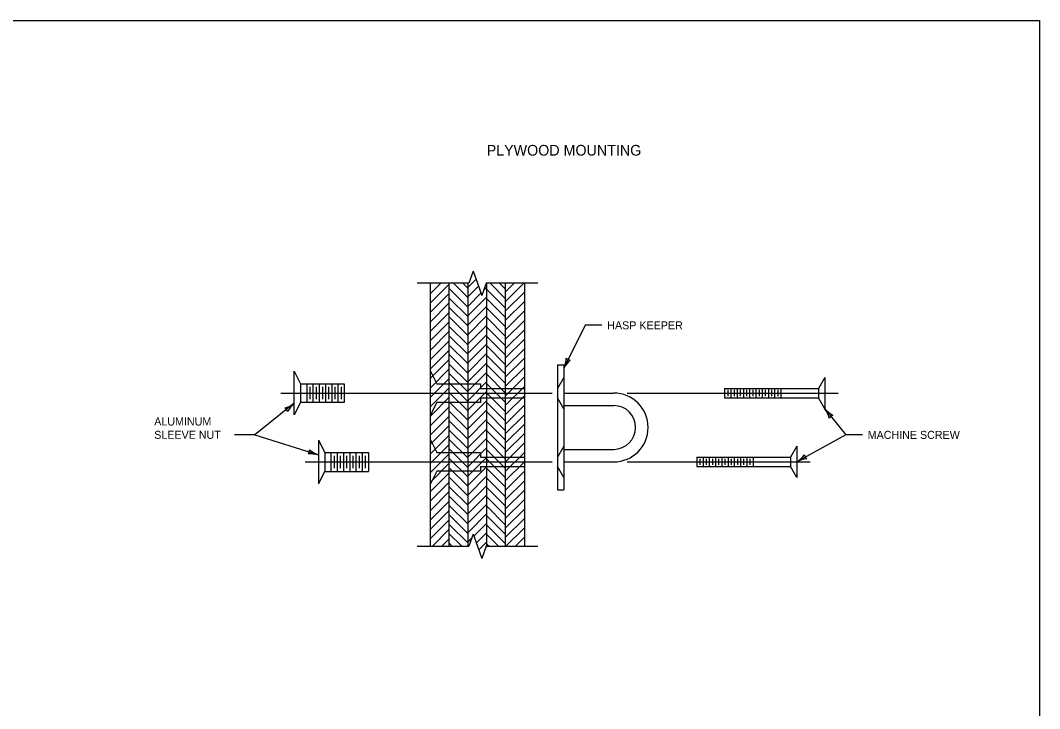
# Model space of a CAD drawing. Extents: x 49991.4 to 50021, y 49987.6 to 50011.4.
# Drawn here: x 50009.11 to 50016.75, y 49993.84 to 49999 of the extents above; entities that cross this region are included whole.
import ezdxf

# ---------------------------------------------------------------- set-up
doc = ezdxf.new("R2010")
doc.units = 0
for name, color, linetype in [('Level 1', 7, 'Continuous'), ('Level 2', 7, 'Continuous'), ('Level 3', 7, 'Continuous'), ('Level 4', 7, 'Continuous'), ('Level 5', 7, 'Continuous'), ('Level 6', 7, 'Continuous')]:
    doc.layers.add(name, color=color, linetype=linetype)

msp = doc.modelspace()

# ---------------------------------------------------------------- linework, layer by layer
at = {"layer": 'Level 1'}
for p, q in [((50012.4648, 49996.9989), (50012.5245, 49997.0586)), ((50012.1836, 49995.0568), (50012.1836, 49997.0284)), ((50012.1836, 49996.9521), (50012.2599, 49997.0284)), ((50012.1836, 49996.8814), (50012.3242, 49997.022)), ((50012.3242, 49995.0568), (50012.3242, 49997.0284)), ((50012.3242, 49996.988), (50012.4648, 49996.8474)), ((50012.3545, 49997.0284), (50012.4648, 49996.9181)), ((50012.4252, 49997.0284), (50012.4648, 49996.9888)), ((50012.4648, 49995.0568), (50012.4648, 49997.0284)), ((50012.4648, 49996.9282), (50012.543, 49997.0064)), ((50012.5804, 49996.9731), (50012.6055, 49996.9982)), ((50012.6058, 49995.0568), (50012.6055, 49997.0284)), ((50012.6055, 49996.9826), (50012.7461, 49996.842)), ((50012.631, 49997.0284), (50012.7461, 49996.9127)), ((50012.7013, 49997.0284), (50012.7461, 49996.9834)), ((50012.7461, 49995.0568), (50012.7461, 49997.0284)), ((50012.7461, 49996.8924), (50012.8821, 49997.0284)), ((50012.7461, 49996.9631), (50012.8114, 49997.0284)), ((50012.8867, 49997.0284), (50012.8867, 49995.0568)), ((50012.1836, 49996.8107), (50012.3242, 49996.9513)), ((50012.3242, 49996.9173), (50012.4648, 49996.7767)), ((50012.4648, 49996.8575), (50012.5615, 49996.9542)), ((50012.4648, 49996.7868), (50012.6055, 49996.9275)), ((50012.6055, 49996.9119), (50012.7461, 49996.7713)), ((50012.7461, 49996.8217), (50012.8867, 49996.9623)), ((50012.7461, 49996.751), (50012.8867, 49996.8916)), ((50012.1836, 49996.74), (50012.3242, 49996.8806)), ((50012.3242, 49996.8466), (50012.4648, 49996.706)), ((50012.4648, 49996.7161), (50012.6055, 49996.8568)), ((50012.6055, 49996.8412), (50012.7461, 49996.7006)), ((50012.7461, 49996.6803), (50012.8867, 49996.8209)), ((50012.1836, 49996.6693), (50012.3242, 49996.8099)), ((50012.1836, 49996.5986), (50012.3242, 49996.7392)), ((50012.3242, 49996.7759), (50012.4648, 49996.6353)), ((50012.4648, 49996.6454), (50012.6055, 49996.7861)), ((50012.6055, 49996.7705), (50012.7461, 49996.6299)), ((50012.7461, 49996.6095), (50012.8867, 49996.7501)), ((50012.1836, 49996.5279), (50012.3242, 49996.6685)), ((50012.3242, 49996.7052), (50012.4648, 49996.5646)), ((50012.4648, 49996.5747), (50012.6055, 49996.7154)), ((50012.6055, 49996.6997), (50012.7461, 49996.5592)), ((50012.7461, 49996.5388), (50012.8867, 49996.6794)), ((50012.1836, 49996.4572), (50012.3242, 49996.5978)), ((50012.3242, 49996.6345), (50012.4648, 49996.4939)), ((50012.4648, 49996.504), (50012.6055, 49996.6447)), ((50012.6055, 49996.629), (50012.7461, 49996.4885)), ((50012.7461, 49996.4681), (50012.8867, 49996.6087)), ((50012.1836, 49996.3865), (50012.3242, 49996.5271)), ((50012.3242, 49996.5638), (50012.4648, 49996.4232)), ((50012.4648, 49996.4333), (50012.6055, 49996.574)), ((50012.6056, 49996.5583), (50012.7461, 49996.4178)), ((50012.7461, 49996.3974), (50012.8867, 49996.538)), ((50012.1836, 49996.3158), (50012.3242, 49996.4564)), ((50012.3242, 49996.4931), (50012.4648, 49996.3525)), ((50012.4648, 49996.3626), (50012.6055, 49996.5033)), ((50012.4648, 49996.2919), (50012.6055, 49996.4326)), ((50012.6056, 49996.4876), (50012.7461, 49996.347)), ((50012.7461, 49996.3267), (50012.8867, 49996.4673)), ((50011.1612, 49996.0409), (50011.1612, 49996.3691)), ((50011.1612, 49996.3691), (50011.2081, 49996.2753)), ((50012.1836, 49996.2451), (50012.3242, 49996.3857)), ((50012.1836, 49996.0409), (50012.1836, 49996.3691)), ((50012.3242, 49996.4224), (50012.4648, 49996.2818)), ((50012.4648, 49996.2212), (50012.6055, 49996.3619)), ((50012.6056, 49996.4169), (50012.7461, 49996.2763)), ((50012.7461, 49996.256), (50012.8867, 49996.3966)), ((50013.1354, 49996.4162), (50013.1354, 49995.4788)), ((50013.1354, 49996.4162), (50013.1822, 49996.4162)), ((50013.1822, 49996.4162), (50013.1822, 49995.4788)), ((50012.1836, 49996.1744), (50012.3242, 49996.315)), ((50012.3242, 49996.3517), (50012.4648, 49996.2111)), ((50012.3242, 49996.2809), (50012.4648, 49996.1403)), ((50012.4648, 49996.1504), (50012.6055, 49996.2911)), ((50012.6056, 49996.3461), (50012.7461, 49996.2056)), ((50012.7461, 49996.1853), (50012.8867, 49996.3259)), ((50015.1385, 49996.3222), (50015.0917, 49996.2402)), ((50015.1385, 49996.3222), (50015.1385, 49996.0878)), ((50011.2081, 49996.2753), (50011.2081, 49996.1347)), ((50011.2081, 49996.2753), (50011.5362, 49996.2753)), ((50011.2549, 49996.2753), (50011.2549, 49996.1347)), ((50011.2784, 49996.2519), (50011.2784, 49996.1582)), ((50011.3018, 49996.2753), (50011.3018, 49996.1347)), ((50011.3253, 49996.2519), (50011.3253, 49996.1582)), ((50011.3487, 49996.2753), (50011.3487, 49996.1347)), ((50011.3722, 49996.2519), (50011.3722, 49996.1582)), ((50011.3956, 49996.2753), (50011.3956, 49996.1347)), ((50011.419, 49996.2519), (50011.419, 49996.1582)), ((50011.4424, 49996.2753), (50011.4424, 49996.1347)), ((50011.4659, 49996.2519), (50011.4659, 49996.1582)), ((50011.4893, 49996.2753), (50011.4893, 49996.1347)), ((50011.5128, 49996.2519), (50011.5128, 49996.1582)), ((50011.5362, 49996.2753), (50011.5362, 49996.1347)), ((50012.1836, 49996.1037), (50012.3242, 49996.2443)), ((50012.3242, 49996.2102), (50012.4648, 49996.0696)), ((50012.4648, 49996.0797), (50012.6055, 49996.2204)), ((50012.6056, 49996.2754), (50012.7461, 49996.1349)), ((50012.6056, 49996.2047), (50012.7461, 49996.0642)), ((50012.7461, 49996.1146), (50012.8867, 49996.2552)), ((50013.1822, 49996.205), (50013.5572, 49996.205)), ((50014.3885, 49996.2402), (50015.0917, 49996.2402)), ((50014.3885, 49996.2402), (50014.3885, 49996.1699)), ((50014.412, 49996.2285), (50014.412, 49996.1816)), ((50014.4354, 49996.2402), (50014.4354, 49996.1699)), ((50014.4589, 49996.2285), (50014.4589, 49996.1816)), ((50014.4823, 49996.2402), (50014.4823, 49996.1699)), ((50014.5058, 49996.2285), (50014.5058, 49996.1816)), ((50014.5292, 49996.2402), (50014.5292, 49996.1699)), ((50014.5526, 49996.2285), (50014.5526, 49996.1816)), ((50014.576, 49996.2402), (50014.576, 49996.1699)), ((50014.5995, 49996.2285), (50014.5995, 49996.1816)), ((50014.6229, 49996.2402), (50014.6229, 49996.1699)), ((50014.6464, 49996.2285), (50014.6464, 49996.1816)), ((50014.6698, 49996.2402), (50014.6698, 49996.1699)), ((50014.6933, 49996.2285), (50014.6933, 49996.1816)), ((50014.7167, 49996.2402), (50014.7167, 49996.1699)), ((50014.7401, 49996.2285), (50014.7401, 49996.1816)), ((50014.7635, 49996.2402), (50014.7635, 49996.1699)), ((50014.787, 49996.2285), (50014.787, 49996.1816)), ((50014.8104, 49996.2402), (50014.8104, 49996.1699)), ((50015.0917, 49996.2402), (50015.0917, 49996.1699)), ((50011.2081, 49996.1347), (50011.1612, 49996.0409)), ((50011.5362, 49996.1347), (50011.2081, 49996.1347)), ((50012.1836, 49996.0329), (50012.3242, 49996.1735)), ((50012.3242, 49996.1395), (50012.4648, 49995.9989)), ((50012.4648, 49996.009), (50012.6055, 49996.1497)), ((50012.6056, 49996.134), (50012.7461, 49995.9935)), ((50012.7461, 49996.0439), (50012.8867, 49996.1845)), ((50014.3885, 49996.1699), (50015.0917, 49996.1699)), ((50015.1385, 49996.0878), (50015.0917, 49996.1699)), ((50012.1836, 49995.9622), (50012.3242, 49996.1028)), ((50012.3242, 49996.0688), (50012.4648, 49995.9282)), ((50012.4648, 49995.9383), (50012.6055, 49996.079)), ((50012.6056, 49996.0632), (50012.7461, 49995.9228)), ((50012.7461, 49995.9731), (50012.8867, 49996.1137)), ((50013.1822, 49996.1113), (50013.5572, 49996.1113)), ((50012.1836, 49995.8915), (50012.3242, 49996.0321)), ((50012.3242, 49995.9981), (50012.4648, 49995.8575)), ((50012.4648, 49995.8676), (50012.6055, 49996.0083)), ((50012.6057, 49995.9925), (50012.7461, 49995.8521)), ((50012.7461, 49995.9024), (50012.8867, 49996.043)), ((50012.1836, 49995.8208), (50012.3242, 49995.9614)), ((50012.3242, 49995.9274), (50012.4648, 49995.7868)), ((50012.4648, 49995.7969), (50012.6055, 49995.9376)), ((50012.6057, 49995.9218), (50012.7461, 49995.7814)), ((50012.7461, 49995.8317), (50012.8867, 49995.9723)), ((50012.7461, 49995.761), (50012.8867, 49995.9016)), ((50011.3428, 49995.8527), (50011.3428, 49995.5245)), ((50011.3428, 49995.8527), (50011.3897, 49995.7589)), ((50012.1836, 49995.7501), (50012.3242, 49995.8907)), ((50012.1836, 49995.5253), (50012.1836, 49995.8534)), ((50012.1836, 49995.6794), (50012.3242, 49995.82)), ((50012.3242, 49995.8567), (50012.4648, 49995.7161)), ((50012.4648, 49995.7262), (50012.6055, 49995.8669)), ((50012.6057, 49995.8511), (50012.7461, 49995.7107)), ((50012.7461, 49995.6903), (50012.8867, 49995.8309)), ((50011.3897, 49995.7589), (50011.7178, 49995.7589)), ((50011.3897, 49995.7589), (50011.3897, 49995.6183)), ((50011.4366, 49995.7589), (50011.4366, 49995.6183)), ((50011.4835, 49995.7589), (50011.4835, 49995.6183)), ((50011.5303, 49995.7589), (50011.5303, 49995.6183)), ((50011.5772, 49995.7589), (50011.5772, 49995.6183)), ((50011.6241, 49995.7589), (50011.6241, 49995.6183)), ((50011.671, 49995.7589), (50011.671, 49995.6183)), ((50011.7178, 49995.7589), (50011.7178, 49995.6183)), ((50012.1836, 49995.6087), (50012.3242, 49995.7493)), ((50012.3242, 49995.786), (50012.4648, 49995.6454)), ((50012.4648, 49995.6555), (50012.6055, 49995.7962)), ((50012.6057, 49995.7803), (50012.7461, 49995.6399)), ((50012.7461, 49995.6196), (50012.8867, 49995.7602)), ((50013.1822, 49995.7831), (50013.5572, 49995.7831)), ((50014.9294, 49995.8065), (50014.8826, 49995.7246)), ((50014.9294, 49995.8065), (50014.9294, 49995.5722)), ((50011.4601, 49995.7355), (50011.4601, 49995.6418)), ((50011.5069, 49995.7355), (50011.5069, 49995.6418)), ((50011.5538, 49995.7355), (50011.5538, 49995.6418)), ((50011.6007, 49995.7355), (50011.6007, 49995.6418)), ((50011.6476, 49995.7355), (50011.6476, 49995.6418)), ((50011.6944, 49995.7355), (50011.6944, 49995.6418)), ((50012.1836, 49995.538), (50012.3242, 49995.6786)), ((50012.3242, 49995.7153), (50012.4648, 49995.5747)), ((50012.4648, 49995.5848), (50012.6055, 49995.7255)), ((50012.6057, 49995.7096), (50012.7461, 49995.5692)), ((50012.7461, 49995.5489), (50012.8867, 49995.6895)), ((50013.1822, 49995.6894), (50013.5572, 49995.6894)), ((50014.1794, 49995.7246), (50014.8826, 49995.7246)), ((50014.1794, 49995.7246), (50014.1794, 49995.6542)), ((50014.2029, 49995.7129), (50014.2029, 49995.666)), ((50014.2263, 49995.7246), (50014.2263, 49995.6542)), ((50014.2498, 49995.7129), (50014.2498, 49995.666)), ((50014.2732, 49995.7246), (50014.2732, 49995.6542)), ((50014.2967, 49995.7129), (50014.2967, 49995.666)), ((50014.3201, 49995.7246), (50014.3201, 49995.6542)), ((50014.3435, 49995.7129), (50014.3435, 49995.666)), ((50014.3669, 49995.7246), (50014.3669, 49995.6542)), ((50014.3904, 49995.7129), (50014.3904, 49995.666)), ((50014.4138, 49995.7246), (50014.4138, 49995.6542)), ((50014.4373, 49995.7129), (50014.4373, 49995.666)), ((50014.4607, 49995.7246), (50014.4607, 49995.6542)), ((50014.4842, 49995.7129), (50014.4842, 49995.666)), ((50014.5076, 49995.7246), (50014.5076, 49995.6542)), ((50014.531, 49995.7129), (50014.531, 49995.666)), ((50014.5544, 49995.7246), (50014.5544, 49995.6542)), ((50014.5779, 49995.7129), (50014.5779, 49995.666)), ((50014.6013, 49995.7246), (50014.6013, 49995.6542)), ((50014.8826, 49995.7246), (50014.8826, 49995.6542)), ((50011.3428, 49995.5245), (50011.3897, 49995.6183)), ((50011.3897, 49995.6183), (50011.7178, 49995.6183)), ((50012.1836, 49995.4673), (50012.3242, 49995.6079)), ((50012.3242, 49995.6445), (50012.4648, 49995.5039)), ((50012.4648, 49995.514), (50012.6055, 49995.6547)), ((50012.6057, 49995.6389), (50012.7461, 49995.4985)), ((50012.7461, 49995.4782), (50012.8867, 49995.6188)), ((50014.1794, 49995.6542), (50014.8826, 49995.6542)), ((50014.9294, 49995.5722), (50014.8826, 49995.6542)), ((50012.1836, 49995.3965), (50012.3242, 49995.5371)), ((50012.3242, 49995.5738), (50012.4648, 49995.4332)), ((50012.4648, 49995.4433), (50012.6055, 49995.584)), ((50012.6057, 49995.5682), (50012.7461, 49995.4278)), ((50012.7461, 49995.4075), (50012.8867, 49995.5481)), ((50012.1836, 49995.3258), (50012.3242, 49995.4664)), ((50012.3242, 49995.5031), (50012.4648, 49995.3625)), ((50012.4648, 49995.3726), (50012.6055, 49995.5133)), ((50012.4648, 49995.3019), (50012.6055, 49995.4426)), ((50012.6057, 49995.4975), (50012.7461, 49995.3571)), ((50012.7461, 49995.3368), (50012.8867, 49995.4774)), ((50013.1354, 49995.4788), (50013.1822, 49995.4788)), ((50012.1836, 49995.2551), (50012.3242, 49995.3957)), ((50012.3242, 49995.4324), (50012.4648, 49995.2918)), ((50012.3242, 49995.3617), (50012.4648, 49995.2211)), ((50012.4648, 49995.2312), (50012.6055, 49995.3719)), ((50012.6058, 49995.4267), (50012.7461, 49995.2864)), ((50012.7461, 49995.266), (50012.8867, 49995.4066)), ((50012.1836, 49995.1844), (50012.3242, 49995.325)), ((50012.3242, 49995.291), (50012.4648, 49995.1504)), ((50012.4648, 49995.1605), (50012.6055, 49995.3012)), ((50012.6058, 49995.356), (50012.7461, 49995.2157)), ((50012.6058, 49995.2853), (50012.7461, 49995.1447)), ((50012.7461, 49995.1953), (50012.8867, 49995.3359)), ((50012.1836, 49995.1137), (50012.3242, 49995.2543)), ((50012.3242, 49995.2203), (50012.4648, 49995.0797)), ((50012.5081, 49995.1331), (50012.6055, 49995.2305)), ((50012.6058, 49995.2146), (50012.7461, 49995.074)), ((50012.7461, 49995.1246), (50012.8867, 49995.2652)), ((50012.1974, 49995.0568), (50012.3242, 49995.1836)), ((50012.3242, 49995.1496), (50012.417, 49995.0568)), ((50012.5266, 49995.0809), (50012.6055, 49995.1598)), ((50012.6058, 49995.1439), (50012.6927, 49995.0568)), ((50012.749, 49995.0568), (50012.8867, 49995.1945)), ((50012.2681, 49995.0568), (50012.3242, 49995.1129)), ((50012.3242, 49995.0789), (50012.3463, 49995.0568)), ((50012.4648, 49995.0898), (50012.4916, 49995.1166)), ((50012.5451, 49995.0287), (50012.6055, 49995.0891)), ((50012.6058, 49995.0732), (50012.6222, 49995.0568)), ((50012.8197, 49995.0568), (50012.8867, 49995.1238))]:
    msp.add_line(p, q, dxfattribs=at)
msp.add_lwpolyline([(49999.3835, 49998.9992), (50016.7501, 49998.9992), (50016.7501, 49987.7988), (49999.3835, 49987.7988)], close=True, dxfattribs=at)
for radius in [0.2578, 0.1641]:
    msp.add_arc((50013.5572, 49995.9472), radius, 270, 90, dxfattribs=at)
at = {"layer": 'Level 3'}
for p, q in [((50013.3435, 49996.713), (50013.1822, 49996.3925)), ((50013.4684, 49996.713), (50013.3435, 49996.713)), ((50011.1612, 49996.1282), (50010.8656, 49995.8917)), ((50015.1385, 49996.0878), (50015.2961, 49995.8917)), ((50010.8664, 49995.8921), (50010.7128, 49995.8921)), ((50010.8656, 49995.8917), (50011.3428, 49995.7415)), ((50015.2961, 49995.8917), (50014.9294, 49995.6896)), ((50015.421, 49995.8917), (50015.2961, 49995.8917))]:
    msp.add_line(p, q, dxfattribs=at)
for centre, radius, start, end in [((50012.9692, 49996.4868), 0.233, 336.11266, 355.36251), ((50013.3765, 49996.2845), 0.2223, 130.74136, 150.92487), ((50013.2398, 49996.507), 0.0548, 225.42417, 261.14653), ((50011.0296, 49996.3074), 0.2223, 286.12093, 306.30443), ((50011.3156, 49995.9537), 0.233, 131.49223, 150.74208), ((50011.0611, 49996.0481), 0.0548, 20.80373, 56.52609), ((50014.9596, 49995.9558), 0.2223, 16.24368, 36.42719), ((50015.3127, 49996.2425), 0.233, 221.61498, 240.86483), ((50015.2188, 49995.9879), 0.0548, 110.92649, 146.64885), ((50011.2205, 49995.78), 0.0548, 324.66271, 0.38507), ((50011.2839, 49995.5161), 0.233, 75.3512, 94.60105), ((50011.4182, 49995.9506), 0.2223, 229.9799, 250.16341), ((50014.807, 49995.8879), 0.233, 301.68445, 320.9343), ((50015.0286, 49995.4906), 0.2223, 96.31315, 116.49666), ((50015.0417, 49995.7515), 0.0548, 190.99596, 226.71832)]:
    msp.add_arc(centre, radius, start, end, dxfattribs=at)
at = {"layer": 'Level 4'}
for p, q in [((50012.1836, 49996.3691), (50012.2305, 49996.2753)), ((50013.1829, 49996.3224), (50013.136, 49996.2404)), ((50012.2305, 49996.2753), (50012.5586, 49996.2753)), ((50012.5586, 49996.2753), (50012.5586, 49996.2399)), ((50012.5586, 49996.2399), (50012.8866, 49996.2399)), ((50012.2305, 49996.1347), (50012.1836, 49996.0409)), ((50012.5586, 49996.1347), (50012.2305, 49996.1347)), ((50012.5586, 49996.1696), (50012.8866, 49996.1696)), ((50012.5586, 49996.1696), (50012.5586, 49996.1347)), ((50013.1829, 49996.088), (50013.136, 49996.1701)), ((50012.1836, 49995.8534), (50012.2305, 49995.7597)), ((50012.2305, 49995.7597), (50012.5586, 49995.7597)), ((50012.5586, 49995.7597), (50012.5586, 49995.7242)), ((50013.1834, 49995.8069), (50013.1365, 49995.7249)), ((50012.5586, 49995.7242), (50012.8869, 49995.7242)), ((50012.2305, 49995.619), (50012.1836, 49995.5253)), ((50012.5586, 49995.619), (50012.2305, 49995.619)), ((50012.5586, 49995.6538), (50012.8869, 49995.6538)), ((50012.5586, 49995.6538), (50012.5586, 49995.619)), ((50013.1834, 49995.5725), (50013.1365, 49995.6546))]:
    msp.add_line(p, q, dxfattribs=at)
at = {"layer": 'Level 5'}
for p, q in [((50011.0612, 49996.205), (50011.6723, 49996.205)), ((50011.6723, 49996.205), (50013.0954, 49996.205)), ((50013.6572, 49996.205), (50014.2721, 49996.205)), ((50014.2721, 49996.205), (50015.2385, 49996.205)), ((50011.2428, 49995.6894), (50013.0954, 49995.6894)), ((50013.6573, 49995.6894), (50014.063, 49995.6894)), ((50014.063, 49995.6894), (50015.0294, 49995.6894))]:
    msp.add_line(p, q, dxfattribs=at)
at = {"layer": 'Level 6'}
for p, q in [((50012.5028, 49997.1198), (50012.4704, 49997.0284)), ((50012.5028, 49997.1198), (50012.5352, 49997.0284)), ((50012.4704, 49997.0284), (50012.0836, 49997.0284)), ((50012.5352, 49997.0284), (50012.5676, 49996.937)), ((50012.6, 49997.0284), (50012.5676, 49996.937)), ((50012.9867, 49997.0284), (50012.6, 49997.0284)), ((50012.5028, 49995.1482), (50012.4704, 49995.0568)), ((50012.5028, 49995.1482), (50012.5352, 49995.0568)), ((50012.0836, 49995.0568), (50012.4704, 49995.0568)), ((50012.5352, 49995.0568), (50012.5676, 49994.9654)), ((50012.6, 49995.0568), (50012.5676, 49994.9654)), ((50012.6, 49995.0568), (50012.9867, 49995.0568))]:
    msp.add_line(p, q, dxfattribs=at)

# ---------------------------------------------------------------- texts
at = {"layer": 'Level 2'}
for s, height, p in [('PLYWOOD MOUNTING', 0.08, (50012.6042, 49997.9855)), ('HASP KEEPER', 0.06, (50013.5084, 49996.683)), ('ALUMINUM', 0.06, (50010.1115, 49995.9621)), ('SLEEVE NUT', 0.06, (50010.1115, 49995.8621)), ('MACHINE SCREW', 0.06, (50015.461, 49995.8617))]:
    msp.add_text(s, height=height, dxfattribs=at).set_placement(p)

doc.saveas('drawing.dxf')
